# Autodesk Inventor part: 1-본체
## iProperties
Created: 2014-12
Part Number: 1-본체
Document SubType Name: Modeling
Designer: Administrator
Density: 2.71 g/cm^3
Material: 알루미늄-6061
Mass: 480.637 g
Surface Area: 683.089 cm^2
Volume: 177.357 cm^3
Author: Administrator
